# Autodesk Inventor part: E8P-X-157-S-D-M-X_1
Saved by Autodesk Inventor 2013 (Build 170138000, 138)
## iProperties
Created: 2012-07
Part Number: E8P-X-157-S-D-M-X_1
Material: Allgemein
Document SubType Name: Modeling
Designer: rYan
Density: 1 g/cm^3
Mass: 0.369495 g
Surface Area: 10.5695 cm^2
Volume: 0.369495 cm^3
Author: rYan
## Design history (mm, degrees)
node "E8P-X-157-S-D-M-X_11"
node "E8P-X-157-S-D-M-X_1"
node "Basis1"
